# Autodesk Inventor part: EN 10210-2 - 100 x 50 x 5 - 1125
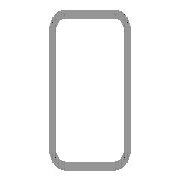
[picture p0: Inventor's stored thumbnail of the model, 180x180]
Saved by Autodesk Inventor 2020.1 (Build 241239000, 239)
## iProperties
Created: 2019-01
Part Number: EN 10210-2 - 100 x 50 x 5 - 1125
Material: Stahl, weich
Description: Rohrleitung
Document SubType Name: Modeling
Standard: DIN
Designer: lutzd
Standard Revision: 2006-07
Standards Organization: DIN
Language: de-DE
Size Designation: 100 x 50 x 5
Categories: <MemberInstance><Categories><Category DisplayName="Profile" InternalName="089c4875-fa83-4c05-b084-43b9cc11f5ed" Mnemonic="GRDR"><CategoryParameter DisplayName="
Stock Number: 100 x 50 x 5
Mass: 12126.8 g
Surface Area: 6086.04 cm^2
Volume: 1544.82 cm^3
Density: 7.85 g/cm^3
Appearance: Semi-Polished(8)
G_W: 50,000 mm
G_H: 100,000 mm
+672893CA-32DF-4640-9157-DBF82B0099B7+SCHNITTDETAIL1: Schnittwinkel 90,00 grd
G_L: 1125,000 mm
DocNumber: ADSK-014250
Folder: .
Dimensions: 50x100x1125 mm
Mass: 12,127 kg
IsCustomPart: 1
_CCFamilyMember: 159
_CCFamilyDisplayName: DIN EN 10210-2 (USAS B17.1 rechteckig) - Rohrleitung — In Klammern angegebene Größen wurden aufgehoben
_FrameMemberDoc: Frame Member File
_Version: 15.0.0
_GetPNFromCC: 1
Title: Profil-Bauteil
Author: lutzd
Revision Number: -
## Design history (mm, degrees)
node "Startebene"
node "Endebene"
sketch "Skizze"
  geometry: L1 (-25, -42.5)-(-25, 42.5); L2 (-17.5, 50)-(17.5, 50); L3 (25, 42.5)-(25, -42.5); L4 (17.5, -50)-(-17.5, -50); L5 (-15, 45)-(15, 45); L6 (20, 40)-(20, -40); L7 (15, -45)-(-15, -45); L8 (-20, -40)-(-20, 40); L9 (0, 72.175)-(0, -72.175) reference; L10 (-37.175, 0)-(37.175, 0) reference; A1 r 7.5 centre (-17.5, -42.5) between (-25, -42.5) and (-17.5, -50); A2 r 7.5 centre (-17.5, 42.5) between (-17.5, 50) and (-25, 42.5); A3 r 7.5 centre (17.5, 42.5) between (25, 42.5) and (17.5, 50); A4 r 7.5 centre (17.5, -42.5) between (17.5, -50) and (25, -42.5); A5 r 5 centre (-15, -40) between (-20, -40) and (-15, -45); A6 r 5 centre (-15, 40) between (-15, 45) and (-20, 40); A7 r 5 centre (15, 40) between (20, 40) and (15, 45); A8 r 5 centre (15, -40) between (15, -45) and (20, -40)
  constraints: 16 end point, 16 point on circle, 16 tangent, 8 centre point, 6 equal radius, 4 parallel, 2 perpendicular, 2 other
  dimensions: "d7" = 7.5 radius of A1 (= G_IR); "d10" = 100 distance between parallel lines of L2 L4 (= G_H); "d11" = 50 distance between parallel lines of L1 L3 (= G_W); "d12" = 5 distance between parallel lines of L3 L6 (= G_T); "d15" = 50 distance between parallel lines of L2 L10 (= 0.5 x d10); "d16" = 25 distance between parallel lines of L9 L3 (= 0.5 x d11); "d19" = 5 radius of A5 (= G_T); "d20" = 5 distance between parallel lines of L4 L7 (= G_T)
extrude "Körper" new body sketch "Skizze" stored distance "d3" = 1125 (= G_L); taper "d4" = 0 deg
node "Driven Length"
  sketch "Sketch3"
    geometry: L1 (0, 0)-(10, 0) reference
    constraints: 2 end point, 1 horizontal
  workplane "Work Plane3"
  sketch "Sketch4"
    geometry: L1 (-2, 0)-(12, 0) reference; L2 (-2, 1125)-(12, 1125) reference
    dimensions: "d18" = 1125 distance between parallel lines of L1 L2 (derived)
workplane "Arbeitsebene4"
feature "Trennen1"
body "Solid1"
other parameters: "G_W" = 50 [user parameter; used in 1 equation term], "G_H" = 100 [user parameter; used in 1 equation term], "G_T" = 5 [user parameter; used in 3 equation terms], "G_IR" = 7.5 [user parameter; used in 1 equation term], "G_L" = 1125 (= d18) [user parameter; used in 1 equation term], "G_OFFSET_START" = 0 [user parameter; used in 1 equation term], "G_OFFSET_END" = 566 [user parameter; used in 1 equation term], "d13" = 0 (computed from G_OFFSET_START), "d14" = 1125 (= G_OFFSET_END + B_L), "B_L" = 559 [user parameter; used in 1 equation term], "d17" = 90 deg
